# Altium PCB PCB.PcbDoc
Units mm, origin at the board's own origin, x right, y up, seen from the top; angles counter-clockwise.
Board outline 20.32 x 10.16 mm, 2 copper layers (Top Layer, Bottom Layer); 16 components, 10 nets, 52 pads, 0 vias.
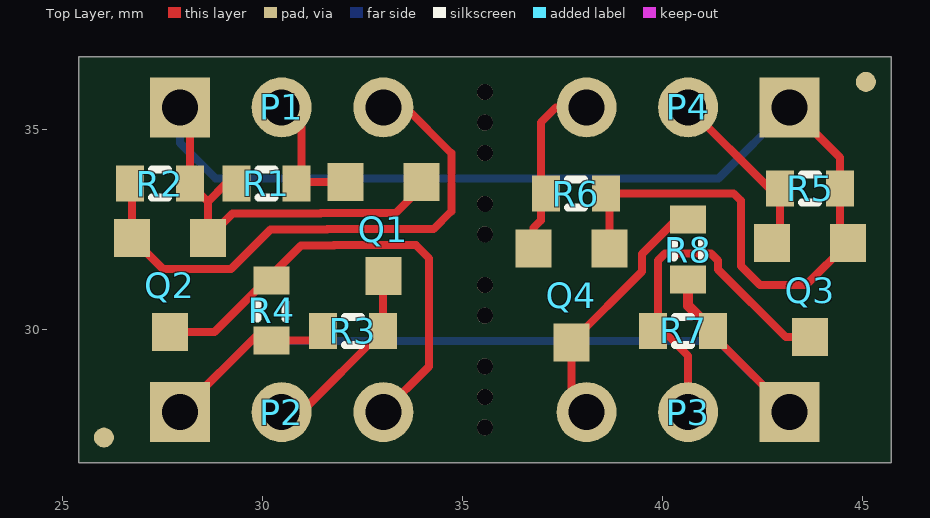
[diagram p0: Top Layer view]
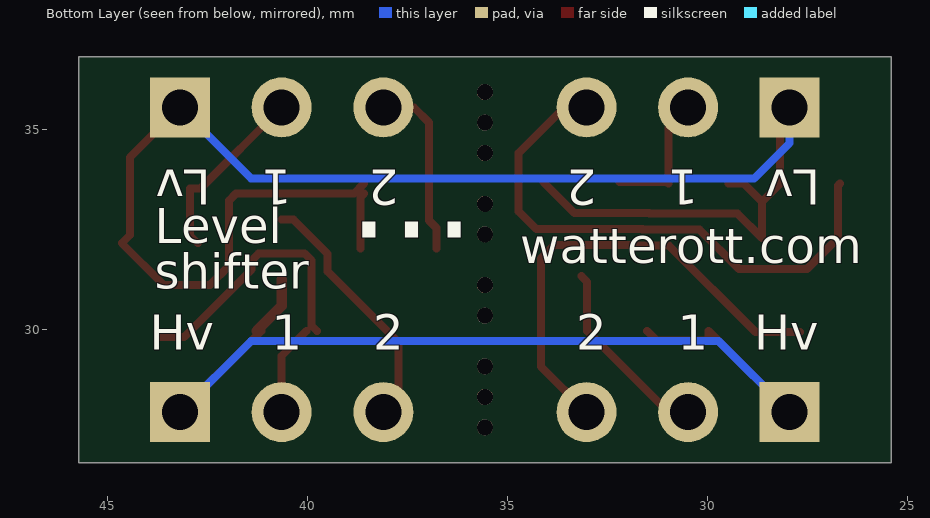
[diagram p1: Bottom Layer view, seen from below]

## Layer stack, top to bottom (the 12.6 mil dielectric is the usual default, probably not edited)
Top Layer: signal copper 0.0356
Dielectric: dielectric 0.32, FR-4, Dk 4.8
Bottom Layer: signal copper 0.0356

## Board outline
25.4,36.83 25.4,26.67 45.72,26.67 45.72,36.83

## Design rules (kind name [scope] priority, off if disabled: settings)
Clearance [All] p1: gap=0.2
PolygonConnect [All] p1: connectstyle=Relief reliefconductorwidth=0.254 reliefentries=4 polygonreliefangle="90 Angle"
RoomDefinition Sheet1 [InComponentClass('Sheet1')] p1: confinementstyle=ConfineIn formatcopy=TRUE lockcomponents=FALSE outline 25.4,26.67 45.72,26.67 45.72,36.83 25.4,36.83
RoutingVias [All] p1: holewidth=0.711 width=1.27 viastyle="Through Hole" minholewidth=0.711 minwidth=1.27 maxholewidth=0.711 maxwidth=1.27
SilkscreenOverComponentPads [All] p1: minsilkscreentomaskgap=0.254
SolderMaskExpansion [All] p1: expansion=0.102
Width [All] p1: maxlimit=0.254 minlimit=0.2 preferedwidth=0.254
27 further rules are at their usual default settings.

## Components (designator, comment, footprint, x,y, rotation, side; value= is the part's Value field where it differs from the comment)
P1 "Lv" HDR1X3 27.94,35.56 r0 top
P2 "Hv" HDR1X3 27.94,27.94 r0 top
P3 "Hv" HDR1X3 43.18,27.94 r180 top
P4 "Lv" HDR1X3 43.18,35.56 r180 top
Q1 "BSS138" SOT23 33.02,32.512 r180 top
Q2 "BSS138" SOT23 27.686,31.115 r180 top
Q3 "BSS138" SOT23 43.688,30.988 r180 top
Q4 "BSS138" SOT23 37.719,30.861 r180 top
R1 "4k7" J1-0603 30.099,33.655 r180 top
R2 "4k7" J1-0603 27.432,33.655 r0 top
R3 "4k7" J1-0603 32.258,29.972 r180 top
R4 "4k7" J1-0603 30.226,30.48 r270 top
R5 "4k7" J1-0603 43.688,33.528 r0 top
R6 "4k7" J1-0603 37.834,33.401 r0 top
R7 "4k7" J1-0603 40.513,29.972 r0 top
R8 "4k7" J1-0603 40.64,32.004 r270 top

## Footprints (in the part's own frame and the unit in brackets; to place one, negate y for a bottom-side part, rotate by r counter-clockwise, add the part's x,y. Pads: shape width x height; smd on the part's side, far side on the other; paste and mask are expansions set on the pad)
HDR1X3 [mm] "Connector; Header; 3 Position"
  rect 1.5x1.5 hole 0.9: 1(0,0)
  round 1.5 hole 0.9: 2(2.54,0) 3(5.08,0)
J1-0603 [mm] "Chip Resistor, Body 1.6x0.8mm, IPC High Density"
  rect 0.7x0.9 smd: 1(-0.75,0) 2(0.75,0)
  silkscreen extent -0.2,-0.35 0.2,0.35, body extent -0.85,-0.48 0.85,0.48, height 0.9
SOT23 [mm] "SOT-23; 3 Leads; Body 3.1 x 2.5 mm, inc. leads (LxW max), Alternate Lead Configuration"
  rect 0.9x0.95 smd: 1(0,1.175) 2(0.95,-1.175) 3(-0.95,-1.175)

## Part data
P1 P2 P3 P4: library part "Header 3", "Header, 3-Pin"
Q1 Q2 Q3 Q4: "N-Channel Enhancement Mode Vertical DMOS FET"
R1 R2 R3 R4 R5 R6 R7 R8: library part Res3, "Resistor"

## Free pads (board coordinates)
  round 0.5 smd: 0(26.035,27.305) 1(45.085,36.195)
  round 0.4 hole 0.4 unplated: 2(35.56,27.559) 3(35.56,28.321) 4(35.56,29.083) 5(35.56,30.353) 6(35.56,31.115) 7(35.56,32.385) 7(35.56,33.147) 8(35.56,34.417) 9(35.56,35.179) 10(35.56,35.941)

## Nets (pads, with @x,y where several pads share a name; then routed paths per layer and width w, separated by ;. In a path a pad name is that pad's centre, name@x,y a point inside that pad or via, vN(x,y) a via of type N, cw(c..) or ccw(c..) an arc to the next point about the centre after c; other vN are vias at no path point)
NetP1_2: P1.2 Q1.2 R1.1 | length 3.3
  Top Layer w0.2: P1.2 30.976,35.064 30.976,33.655 31.008,33.687 Q1.2@32.197,33.687
NetP1_3: P1.3 Q2.2 R2.1 | length 13.9
  Top Layer w0.2: R2.1 26.736,33.601 Q2.2 27.511,31.515 29.21,31.515 30.2,32.505 31.616,32.505 31.623,32.512 34.271,32.512 34.72,32.961 34.72,34.413 33.573,35.56 P1.3
NetP2_2: P2.2 Q1.1 R3.1 | length 4.8
  Top Layer w0.2: P2.2 30.976,27.94 R3.1 33.008,31.198 Q1.1@33.147,31.337
NetP2_3: P2.3 Q2.1 R4.1 | length 11.8
  Top Layer w0.2: Q2.1 28.797,29.94 30.962,32.105 31.782,32.105 31.789,32.112 33.836,32.112 34.163,31.785 34.163,29.083 P2.3
NetP3_2: P3.2 Q3.1 R7.1 | length 9
  Top Layer w0.2: R7.1 39.89,30.099 39.89,31.728 40.066,31.904 41.214,31.904 41.39,31.728 41.39,31.508 43.085,29.813 Q3.1 ; R7.1@40.017,29.972 40.64,29.349 P3.2
NetP3_3: P3.3 Q4.1 R8.1 | length 6.4
  Top Layer w0.2: P3.3 37.719,28.321 Q4.1 39.49,31.457 39.49,31.894 40.35,32.754 R8.1
NetP4_2: P4.2 Q3.2 R5.1 | length 4.6
  Top Layer w0.2: P4.2 42.672,33.528 R5.1 42.938,32.363 Q3.2
NetP4_3: P4.3 Q4.2 R6.1 | length 4.5
  Top Layer w0.2: Q4.2 36.769,32.544 36.957,32.732 36.957,35.179 37.338,35.56 P4.3
V_HV: P2.1 P3.1 R3.2 R4.2 R7.2 R8.2 | length 25.9
  Top Layer w0.2: P2.1 29.972,29.972 29.972,29.73 31.266,29.73 R3.2 ; R7.2@41.148,29.972 P3.1
  Top Layer w0.254: R8.2 40.64,30.595 R7.2
  Bottom Layer w0.2: P2.1 29.718,29.718 41.402,29.718 P3.1
V_LV: P1.1 P4.1 Q1.3 Q2.3 Q3.3 Q4.3 R1.2 R2.2 R5.2 R6.2 | length 41.8
  Top Layer w0.2: P1.1 28.182,35.318 R2.2 28.636,33.201 ; R1.2@29.476,33.655 29.09,33.655 28.636,33.201 ; Q1.3@34.097,33.687 33.322,32.912 31.457,32.912 31.45,32.905 29.251,32.905 Q2.3 28.636,33.201 ; R6.2 38.669,33.316 Q4.3 ; R6.2@38.584,33.655 38.838,33.401 40.063,33.401 40.066,33.404 41.78,33.404 41.959,33.225 41.959,31.593 42.437,31.115 43.59,31.115 Q3.3 44.438,32.363 R5.2 44.438,34.302 P4.1
  Bottom Layer w0.2: P1.1 27.94,34.671 28.829,33.782 41.402,33.782 P4.1

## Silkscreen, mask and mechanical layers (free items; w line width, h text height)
Bottom Overlay:
  text "Lv" at 27.178,34.29 h1.5 r180
  text "1" at 30.226,34.29 h1.5 r180
  text "2" at 32.766,34.29 h1.5 r180
  text "2" at 37.719,34.29 h1.5 r180
  text "1" at 40.386,34.29 h1.5 r180
  text "Lv" at 42.418,34.29 h1.5 r180
  text "Level" at 43.815,31.877 h1.5
  text "watterott.com" at 34.671,31.369 h1.5
  text "⋯" at 38.989,30.734 h4
  text "shifter" at 43.815,30.734 h1.5
  text "Hv" at 28.829,29.21 h1.5
  text "1" at 30.734,29.21 h1.5
  text "2" at 33.274,29.21 h1.5
  text "2" at 38.354,29.21 h1.5
  text "1" at 40.894,29.21 h1.5
  text "Hv" at 43.942,29.21 h1.5
Mechanical 1:
  the board outline again, w0.02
